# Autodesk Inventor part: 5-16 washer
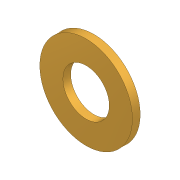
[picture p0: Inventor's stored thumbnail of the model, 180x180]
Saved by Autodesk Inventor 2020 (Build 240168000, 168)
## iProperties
Created: 2020-01
Part Number: 5-16 washer
Material: Brass, Soft Yellow
Document SubType Name: Modeling
Designer: woodk
Density: 8.47 g/cm^3
Appearance: Brass - Satin
Vendor: KoP
Mass: 2.25331 g
Surface Area: 4.82953 cm^2
Volume: 0.266034 cm^3
Author: woodk
Revision Number: ANY
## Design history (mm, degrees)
feature "Imported1"
body "Solid1"
